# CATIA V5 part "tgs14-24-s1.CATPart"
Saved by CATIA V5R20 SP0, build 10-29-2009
Part number: TGS14-24-S1
Definition: design
Nomenclature: TGS14-24-S1
Source: made
Description: NOT SPECIFIED
Bounding box of the stored display mesh (mm): x -22 to 0.8, y 0 to 14, z -6 to 6
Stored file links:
  C:\Users\Raffaele\Desktop\3D X SITO CF\I-MOLD\TGS-S1\tgs14-s1.step\tgs14-24-s1.CATPart
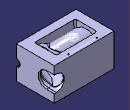
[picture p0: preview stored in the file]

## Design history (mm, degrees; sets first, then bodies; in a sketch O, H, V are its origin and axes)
Set1
  DatumCurve1 "COMPOSITE_CURVE #4173"
  DatumCurve2 "COMPOSITE_CURVE #4225"
  DatumCurve3 "COMPOSITE_CURVE #4304"
  DatumCurve4 "COMPOSITE_CURVE #4347"
  DatumCurve5 "COMPOSITE_CURVE #4576"
  DatumCurve6 "COMPOSITE_CURVE #4717"
  DatumCurve7 "COMPOSITE_CURVE #4744"
  DatumCurve8 "COMPOSITE_CURVE #4802"
  DatumCurve9 "COMPOSITE_CURVE #4857"
  DatumCurve10 "COMPOSITE_CURVE #4886"
  Line1 "LINE #4890": stored without definition
  DatumSurface1 "OPEN_SHELL #4116"
Body1 "MANIFOLD_SOLID_BREP #4117" (main body)
  Solid1: solid without history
